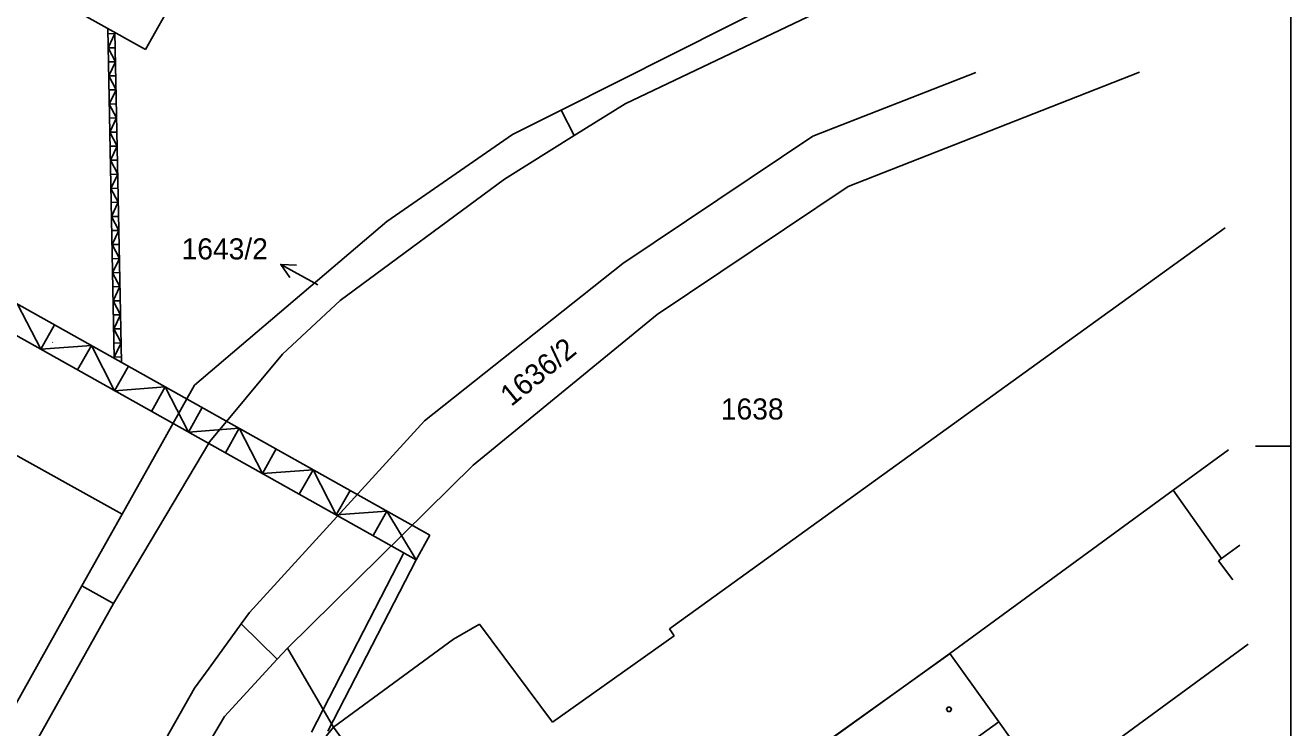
# Model space of a CAD drawing. Extents: x -762592 to -762444, y -1032635 to -1032425.
# Drawn here: x -762533.5 to -762443.5, y -1032549.7 to -1032499.7 of the extents above; entities that cross this region are included whole.
import ezdxf

# ---------------------------------------------------------------- set-up
doc = ezdxf.new("R2010")
doc.units = 0
for name, color, linetype in [('Kabeláž - kabelové vedení NN - stávající', 7, 'Continuous'), ('Katastr - energomost - stávající', 7, 'Continuous'), ('Katastr - hranice parcel', 7, 'Continuous'), ('Katastr - oploceni_budovy aj', 7, 'Continuous'), ('Katastr - parcelní čísla - nedotčené ostatní', 7, 'Continuous'), ('Katastr - vnitřní kresba', 7, 'Continuous'), ('Tisk', 7, 'Continuous')]:
    doc.layers.add(name, color=color, linetype=linetype)

msp = doc.modelspace()

# ---------------------------------------------------------------- linework, layer by layer
at = {"layer": 'Kabeláž - kabelové vedení NN - stávající'}
msp.add_line((-762531.511, -1032522.293), (-762531.523, -1032522.286), dxfattribs=at)
at = {"layer": 'Katastr - energomost - stávající'}
for p, q in [((-762504.709, -1032536.003), (-762587.94, -1032489.333)), ((-762505.687, -1032537.747), (-762587.773, -1032491.719)), ((-762527.139, -1032523.423), (-762527.601, -1032499.973)), ((-762527.094, -1032500.338), (-762527.594, -1032500.348)), ((-762526.633, -1032523.711), (-762527.095, -1032500.252)), ((-762527.074, -1032501.338), (-762527.574, -1032501.347)), ((-762527.054, -1032502.337), (-762527.554, -1032502.347)), ((-762527.034, -1032503.337), (-762527.534, -1032503.347)), ((-762527.015, -1032504.336), (-762527.515, -1032504.346)), ((-762526.995, -1032505.336), (-762527.495, -1032505.346)), ((-762526.975, -1032506.336), (-762527.475, -1032506.345)), ((-762526.956, -1032507.335), (-762527.456, -1032507.345)), ((-762526.936, -1032508.335), (-762527.436, -1032508.345)), ((-762526.916, -1032509.334), (-762527.416, -1032509.344)), ((-762526.897, -1032510.334), (-762527.396, -1032510.344)), ((-762526.877, -1032511.334), (-762527.377, -1032511.343)), ((-762526.857, -1032512.333), (-762527.357, -1032512.343)), ((-762526.837, -1032513.333), (-762527.337, -1032513.343)), ((-762526.818, -1032514.332), (-762527.318, -1032514.342)), ((-762526.798, -1032515.332), (-762527.298, -1032515.342)), ((-762526.778, -1032516.332), (-762527.278, -1032516.342)), ((-762526.759, -1032517.331), (-762527.258, -1032517.341)), ((-762526.739, -1032518.331), (-762527.239, -1032518.341)), ((-762526.719, -1032519.331), (-762527.219, -1032519.34)), ((-762526.699, -1032520.33), (-762527.199, -1032520.34)), ((-762531.395, -1032521.039), (-762532.373, -1032522.784)), ((-762526.68, -1032521.33), (-762527.18, -1032521.34)), ((-762529.747, -1032524.256), (-762528.769, -1032522.512)), ((-762526.66, -1032522.329), (-762527.16, -1032522.339)), ((-762527.14, -1032523.339), (-762526.64, -1032523.329)), ((-762526.143, -1032523.984), (-762527.121, -1032525.729)), ((-762524.495, -1032527.201), (-762523.517, -1032525.457)), ((-762520.89, -1032526.929), (-762521.869, -1032528.674)), ((-762518.264, -1032528.402), (-762519.243, -1032530.146)), ((-762515.638, -1032529.874), (-762516.617, -1032531.619)), ((-762513.012, -1032531.347), (-762513.99, -1032533.091)), ((-762511.364, -1032534.564), (-762510.386, -1032532.819)), ((-762508.738, -1032536.036), (-762507.76, -1032534.292)), ((-762505.687, -1032537.747), (-762504.709, -1032536.003)), ((-762513.136, -1032550), (-762506.559, -1032537.258)), ((-762505.687, -1032537.747), (-762505.687, -1032537.748))]:
    msp.add_line(p, q, dxfattribs=at)
for points in [[(-762527.14, -1032523.339), (-762526.66, -1032522.329), (-762527.18, -1032521.34), (-762526.699, -1032520.33), (-762527.219, -1032519.34), (-762526.739, -1032518.331), (-762527.258, -1032517.341), (-762526.778, -1032516.332), (-762527.298, -1032515.342), (-762526.818, -1032514.332), (-762527.337, -1032513.343), (-762526.857, -1032512.333), (-762527.377, -1032511.343), (-762526.897, -1032510.334), (-762527.416, -1032509.344), (-762526.936, -1032508.335), (-762527.456, -1032507.345), (-762526.975, -1032506.336), (-762527.495, -1032505.346), (-762527.015, -1032504.336), (-762527.534, -1032503.347), (-762527.054, -1032502.337), (-762527.574, -1032501.347), (-762527.094, -1032500.338)], [(-762527.121, -1032525.729), (-762528.769, -1032522.512), (-762532.373, -1032522.784), (-762534.021, -1032519.567), (-762537.625, -1032519.839), (-762539.273, -1032516.622), (-762542.877, -1032516.894), (-762544.525, -1032513.677), (-762548.129, -1032513.949), (-762549.777, -1032510.732), (-762553.382, -1032511.004)], [(-762518.264, -1032528.402), (-762521.869, -1032528.674), (-762523.517, -1032525.457), (-762527.121, -1032525.729)], [(-762505.687, -1032537.747), (-762507.76, -1032534.292), (-762511.364, -1032534.564), (-762513.012, -1032531.347), (-762516.617, -1032531.619), (-762518.264, -1032528.402)], [(-762511.975, -1032549.93), (-762505.687, -1032537.748)]]:
    msp.add_lwpolyline(points, dxfattribs=at)
at = {"layer": 'Katastr - hranice parcel'}
for p, q in [((-762524.93, -1032501.46), (-762509.68, -1032474.3)), ((-762531.74, -1032497.66), (-762524.93, -1032501.46)), ((-762479.47, -1032497.75), (-762495.38, -1032505.77)), ((-762490.84, -1032505.32), (-762475.856, -1032498.201)), ((-762477.49, -1032507.63), (-762465.908, -1032503.112)), ((-762474.98, -1032511.22), (-762454.277, -1032503.078)), ((-762495.38, -1032505.77), (-762498.84, -1032507.51)), ((-762494.46, -1032507.59), (-762495.38, -1032505.77)), ((-762494.46, -1032507.59), (-762490.84, -1032505.32)), ((-762507.76, -1032513.7), (-762498.84, -1032507.51)), ((-762499.41, -1032510.68), (-762494.46, -1032507.59)), ((-762490.99, -1032516.69), (-762477.49, -1032507.63)), ((-762573.74, -1032508.25), (-762526.59, -1032534.51)), ((-762511.09, -1032519.32), (-762499.41, -1032510.68)), ((-762488.56, -1032520.3), (-762474.98, -1032511.22)), ((-762521.43, -1032525.33), (-762507.76, -1032513.7)), ((-762487.69, -1032542.66), (-762448.18, -1032514.16)), ((-762505.1, -1032527.87), (-762490.99, -1032516.69)), ((-762515.19, -1032523.12), (-762511.09, -1032519.32)), ((-762501.63, -1032531.03), (-762488.56, -1032520.3)), ((-762520.35, -1032529.34), (-762515.19, -1032523.12)), ((-762526.59, -1032534.51), (-762521.43, -1032525.33)), ((-762517.52, -1032541.49), (-762505.1, -1032527.87)), ((-762527.19, -1032540.86), (-762520.35, -1032529.34)), ((-762514.83, -1032544.03), (-762501.63, -1032531.03)), ((-762529.44, -1032539.6), (-762526.59, -1032534.51)), ((-762529.44, -1032539.6), (-762554.975, -1032585.241)), ((-762527.19, -1032540.86), (-762529.44, -1032539.6)), ((-762554.188, -1032589.048), (-762527.19, -1032540.86)), ((-762518.12, -1032542.31), (-762517.52, -1032541.49)), ((-762520.41, -1032545.46), (-762518.12, -1032542.31)), ((-762518.12, -1032542.31), (-762515.56, -1032544.82)), ((-762503.03, -1032543.4), (-762501.19, -1032542.32)), ((-762501.19, -1032542.32), (-762495.99, -1032549.29)), ((-762487.69, -1032542.66), (-762487.34, -1032543.15)), ((-762511.56, -1032549.65), (-762503.03, -1032543.4)), ((-762495.99, -1032549.29), (-762487.34, -1032543.15)), ((-762515.56, -1032544.82), (-762514.83, -1032544.03)), ((-762514.83, -1032544.03), (-762511.56, -1032549.65)), ((-762521.44, -1032546.89), (-762520.41, -1032545.46)), ((-762518.25, -1032547.74), (-762515.56, -1032544.82)), ((-762543.41, -1032585.51), (-762521.44, -1032546.89)), ((-762519.3, -1032548.89), (-762518.25, -1032547.74)), ((-762536.08, -1032576.94), (-762519.3, -1032548.89)), ((-762516.38, -1032555.5), (-762511.56, -1032549.65)), ((-762511.56, -1032549.65), (-762504.38, -1032559.56))]:
    msp.add_line(p, q, dxfattribs=at)
at = {"layer": 'Katastr - oploceni_budovy aj'}
msp.add_lwpolyline([(-762479.376, -1032560.128), (-762473.982, -1032556.206), (-762477.506, -1032551.41), (-762467.738, -1032544.427)], dxfattribs=at)
at = {"layer": 'Katastr - parcelní čísla - nedotčené ostatní'}
msp.add_line((-762515.307, -1032516.748), (-762512.684, -1032518.204), dxfattribs=at)
msp.add_lwpolyline([(-762514.675, -1032517.67), (-762515.307, -1032516.748), (-762514.19, -1032516.796)], dxfattribs=at)
msp.add_lwpolyline([(-762467.723, -1032548.237), (-762467.633, -1032548.387), (-762467.723, -1032548.537), (-762467.903, -1032548.537), (-762467.993, -1032548.387), (-762467.903, -1032548.237)], close=True, dxfattribs=at)
at = {"layer": 'Katastr - vnitřní kresba'}
for p, q in [((-762451.87, -1032532.81), (-762447.945, -1032529.943)), ((-762467.76, -1032544.41), (-762451.87, -1032532.81)), ((-762451.87, -1032532.81), (-762448.44, -1032537.66)), ((-762448.44, -1032537.66), (-762447.152, -1032536.712)), ((-762448.65, -1032537.82), (-762448.44, -1032537.66)), ((-762448.65, -1032537.82), (-762447.637, -1032539.182)), ((-762477.46, -1032551.4), (-762467.76, -1032544.41)), ((-762467.76, -1032544.41), (-762464.28, -1032549.27)), ((-762460.77, -1032554.17), (-762446.551, -1032543.759)), ((-762473.92, -1032556.26), (-762464.28, -1032549.27)), ((-762464.28, -1032549.27), (-762460.77, -1032554.17))]:
    msp.add_line(p, q, dxfattribs=at)
at = {"layer": 'Tisk'}
for points in [[(-762446.028, -1032529.685), (-762443.528, -1032529.685), (-762443.528, -1032424.685), (-762592.028, -1032424.685), (-762592.028, -1032529.685), (-762589.528, -1032529.685)], [(-762589.528, -1032529.685), (-762592.028, -1032529.685), (-762592.028, -1032634.685), (-762443.528, -1032634.685), (-762443.528, -1032529.685), (-762446.028, -1032529.685)]]:
    msp.add_lwpolyline(points, dxfattribs=at)

# ---------------------------------------------------------------- texts
at = {"layer": 'Katastr - parcelní čísla - nedotčené ostatní'}
for s, p in [('1643/2', (-762522.359, -1032516.394)), ('1638', (-762484.03, -1032527.78))]:
    msp.add_text(s, height=1.5, dxfattribs=at).set_placement(p)
msp.add_text('1636/2', height=1.5, rotation=39.20558, dxfattribs=at).set_placement((-762498.931, -1032526.9))

doc.saveas('drawing.dxf')
